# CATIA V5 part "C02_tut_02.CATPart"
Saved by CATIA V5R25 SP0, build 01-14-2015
Part number: Part1
Bounding box of the stored display mesh (mm): x 0 to 0, y -60 to 60, z -50 to 50
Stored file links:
  E:\ashutosh\Academics\Catia\CATIA V5-6R2013_partfiles\Tutorials_ver_2\C02_tut_02.CATPart
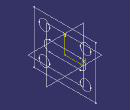
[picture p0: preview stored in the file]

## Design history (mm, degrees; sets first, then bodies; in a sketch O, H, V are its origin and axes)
Body1 (main body)
  Sketch1 on yz-plane, origin (0, 0, 0), H (0, 1, 0), V (0, 0, 1)
    line L1 (60, 50) -> (60, -50)
    line L2 (60, -50) -> (-60, -50)
    line L3 (-60, -50) -> (-60, 50)
    line L4 (-60, 50) -> (60, 50)
    line L5 (-30, 10) -> (30, 10)
    arc A1 centre (30, 0) radius 10 from (30, 10) to (30, -10) cw
    line L6 (30, -10) -> (-30, -10)
    arc A2 centre (-30, 0) radius 10 from (-30, -10) to (-30, 10) cw
    circle A3 centre (40, 30) radius 10
    circle A4 centre (-40, 30) radius 10
    circle A5 centre (40, -30) radius 10
    circle A6 centre (-40, -30) radius 10
    radius A3 = 10
    vertical: L1 V, L3 V
    horizontal: L2 H, L4 H, L5 H
    equidistance: L1 L3 O, L2 L4 O
    tangency: A1 L5, L6 A1, A2 L5, A2 L6
    symmetry: A3 A4 V, A3 A5 H, A4 A6 H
